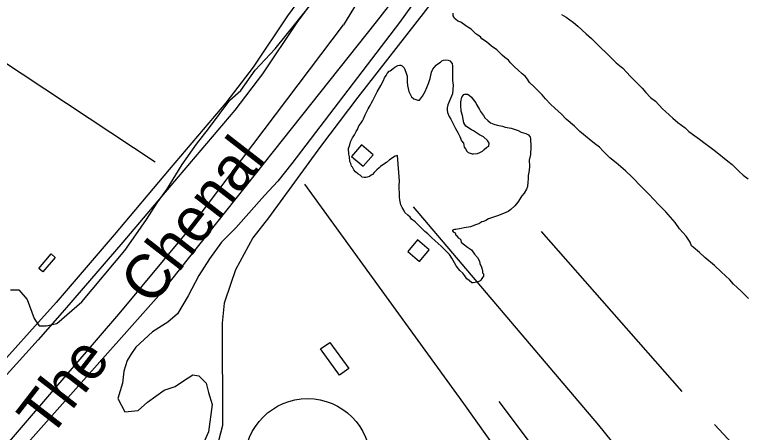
# Model space of a CAD drawing. Extents: x 3263578 to 3301413, y 764927 to 798602.
# Drawn here: x 3276220 to 3278134, y 776528 to 777624 of the extents above; entities that cross this region are included whole.
import ezdxf

# ---------------------------------------------------------------- set-up
doc = ezdxf.new("R2010")
doc.units = 0
for name, color, linetype in [('V-BLDG-OTLN', 7, 'Continuous'), ('V-RIVR-IDEN', 7, 'Continuous'), ('V-ROAD-CNTR', 7, 'Continuous'), ('V-ROAD-IDEN', 7, 'Continuous'), ('V-SITE-VEGE', 7, 'Continuous'), ('V-TOPO-SHOR', 7, 'Continuous')]:
    doc.layers.add(name, color=color, linetype=linetype)

msp = doc.modelspace()

# ---------------------------------------------------------------- linework, layer by layer
at = {"layer": 'V-BLDG-OTLN'}
for points in [[(3277129.6, 777282.6), (3277103.6, 777252.2), (3277134.1, 777226.2), (3277160, 777256.6)], [(3277276.7, 777033), (3277250.8, 777002.6), (3277281.2, 776976.6), (3277307.2, 777007.1)], [(3276326.1, 776987.2), (3276293.7, 776949.1), (3276283, 776958.2), (3276315.4, 776996.2)], [(3277071.9, 776678.4), (3277022.2, 776747.1), (3277046.3, 776764.5), (3277096, 776695.9)]]:
    msp.add_lwpolyline(points, close=True, dxfattribs=at)
at = {"layer": 'V-ROAD-CNTR'}
for points in [[(3277714.9, 778198.6), (3277529.7, 777962.3), (3277399.1, 777774.5), (3277297.3, 777634.4), (3277120, 777407.6), (3277022.1, 777278.4), (3276885.8, 777090.8), (3276844.4, 777038.2)], [(3277194.8, 777970.7), (3277056, 777784.8), (3276935.6, 777620.8), (3276845.7, 777486), (3276773.8, 777392.2), (3276625.5, 777218), (3276480.6, 777046.5), (3276328.4, 776869.2), (3276259.2, 776790.9), (3276145.3, 776665.7), (3276078.7, 776600.9), (3276001.2, 776511.3), (3275907.5, 776403.5), (3275821.9, 776296.9), (3275728.7, 776181.5), (3275680.8, 776116.1), (3275632.5, 776068.6), (3275515.4, 775977.6), (3275428.3, 775913), (3275327.1, 775831.8)], [(3277218.8, 777952.7), (3277080.1, 777766.9), (3276960.2, 777603.6), (3276870.1, 777468.6), (3276797.2, 777373.4), (3276648.4, 777198.6), (3276503.4, 777027.1), (3276351, 776849.5), (3276281.5, 776770.9), (3276166.9, 776644.8), (3276100.5, 776580.2), (3276023.8, 776491.6), (3275930.5, 776384.3), (3275845.3, 776278.1), (3275752.5, 776163.2), (3275703.5, 776096.4), (3275652.3, 776046), (3275533.6, 775953.7), (3275446.6, 775889.2), (3275376.6, 775833.1)], [(3276844.4, 777038.2), (3276799, 776954.4), (3276787, 776918.4), (3276769, 776866.9), (3276764, 776815.1), (3276764.8, 776546.6), (3276754.9, 776506.2), (3276736.4, 776456.2), (3276718.2, 776409.9), (3276692.4, 776372.3), (3276649.2, 776322.2), (3276604.9, 776260.7), (3276427.5, 776073.9), (3276212.2, 775832.8)]]:
    msp.add_lwpolyline(points, dxfattribs=at)
at = {"layer": 'V-ROAD-IDEN'}
msp.add_circle((3276988.1, 776451.9), 165, dxfattribs=at)
at = {"layer": 'V-SITE-VEGE'}
for p, q in [((3277410.4, 777853.7), (3277228.9, 777603.2)), ((3276903.4, 777534.4), (3277066.1, 777737.9)), ((3277369.9, 777621.1), (3277369.8, 777627.3)), ((3277372, 777618.1), (3277369.9, 777621.1)), ((3277373, 777614), (3277372, 777618.1)), ((3277376.1, 777612), (3277373, 777614)), ((3277382.3, 777607), (3277376.1, 777612)), ((3277389.5, 777604), (3277382.3, 777607)), ((3277653.5, 777623.9), (3277665.8, 777616.9)), ((3277665.8, 777616.9), (3277676.1, 777609.9)), ((3277676.1, 777609.9), (3277685.3, 777602.8)), ((3277228.9, 777603.2), (3276947.2, 777233.8)), ((3277402.8, 777594.9), (3277389.5, 777604)), ((3277408, 777590.9), (3277402.8, 777594.9)), ((3277417.2, 777585.9), (3277408, 777590.9)), ((3277685.3, 777602.8), (3277696.6, 777593.7)), ((3277696.6, 777593.7), (3277718.3, 777573.6)), ((3277429.5, 777573.8), (3277417.2, 777585.9)), ((3277434.7, 777569.7), (3277429.5, 777573.8)), ((3277441.9, 777565.7), (3277434.7, 777569.7)), ((3277718.3, 777573.6), (3277732.7, 777561.5)), ((3277445, 777560.7), (3277441.9, 777565.7)), ((3277457.3, 777552.6), (3277445, 777560.7)), ((3277470.7, 777541.5), (3277457.3, 777552.6)), ((3277732.7, 777561.5), (3277755.3, 777538.2)), ((3276850.2, 777478), (3276903.4, 777534.4)), ((3277484, 777531.5), (3277470.7, 777541.5)), ((3277498.5, 777517.3), (3277484, 777531.5)), ((3277755.3, 777538.2), (3277772.8, 777522.1)), ((3277505.7, 777511.3), (3277498.5, 777517.3)), ((3277514.9, 777504.2), (3277505.7, 777511.3)), ((3277772.8, 777522.1), (3277797.6, 777497.8)), ((3277520.1, 777497.1), (3277514.9, 777504.2)), ((3277530.4, 777487), (3277520.1, 777497.1)), ((3277797.6, 777497.8), (3277815, 777483.7)), ((3276812.7, 777424.8), (3276850.2, 777478)), ((3277539.6, 777479), (3277530.4, 777487)), ((3277551, 777468.9), (3277539.6, 777479)), ((3277815, 777483.7), (3277834.6, 777461.5)), ((3277558.2, 777462.8), (3277551, 777468.9)), ((3277564.4, 777454.7), (3277558.2, 777462.8)), ((3277569.6, 777445.6), (3277564.4, 777454.7)), ((3277834.6, 777461.5), (3277865.6, 777431.2)), ((3277581.9, 777434.5), (3277569.6, 777445.6)), ((3277603.5, 777413.3), (3277581.9, 777434.5)), ((3276784.5, 777399.7), (3276812.7, 777424.8)), ((3277865.6, 777431.2), (3277874.8, 777420)), ((3277874.8, 777420), (3277887.2, 777406.9)), ((3276756.3, 777362.2), (3276784.5, 777399.7)), ((3277611.8, 777403.2), (3277603.5, 777413.3)), ((3277625.2, 777389), (3277611.8, 777403.2)), ((3277887.2, 777406.9), (3277900.6, 777396.8)), ((3277900.6, 777396.8), (3277919.1, 777376.6)), ((3277636.5, 777378.9), (3277625.2, 777389)), ((3277654, 777362.8), (3277636.5, 777378.9)), ((3277919.1, 777376.6), (3277926.4, 777369.5)), ((3276728.2, 777324.6), (3276756.3, 777362.2)), ((3277666.4, 777349.6), (3277654, 777362.8)), ((3277926.4, 777369.5), (3277945.9, 777352.4)), ((3277688, 777331.5), (3277666.4, 777349.6)), ((3277945.9, 777352.4), (3277959.3, 777341.3)), ((3277959.3, 777341.3), (3277977.8, 777327.2)), ((3276696.9, 777283.9), (3276728.2, 777324.6)), ((3277702.4, 777317.3), (3277688, 777331.5)), ((3277977.8, 777327.2), (3277988.1, 777317.1)), ((3277726.1, 777297.2), (3277702.4, 777317.3)), ((3277988.1, 777317.1), (3278003.5, 777306)), ((3278003.5, 777306), (3278015.8, 777297)), ((3276659.3, 777230.7), (3276696.9, 777283.9)), ((3277740.5, 777286.1), (3277726.1, 777297.2)), ((3277753.8, 777276), (3277740.5, 777286.1)), ((3278015.8, 777297), (3278030.2, 777285.9)), ((3278030.2, 777285.9), (3278040.5, 777278.8)), ((3277763.1, 777265.9), (3277753.8, 777276)), ((3277780.6, 777248.7), (3277763.1, 777265.9)), ((3278040.5, 777278.8), (3278058, 777265.7)), ((3278058, 777265.7), (3278089.8, 777239.5)), ((3277797.1, 777235.6), (3277780.6, 777248.7)), ((3276618.6, 777164.9), (3276659.3, 777230.7)), ((3276947.2, 777233.8), (3276909.7, 777186.8)), ((3277821.8, 777214.4), (3277797.1, 777235.6)), ((3278089.8, 777239.5), (3278101.2, 777230.5)), ((3278101.2, 777230.5), (3278118.7, 777213.3)), ((3277839.3, 777197.3), (3277821.8, 777214.4)), ((3278118.7, 777213.3), (3278130, 777203.2)), ((3276909.7, 777186.8), (3276875.2, 777149.3)), ((3277864, 777172), (3277839.3, 777197.3)), ((3278130, 777203.2), (3278143.4, 777193.1)), ((3277882.6, 777152.8), (3277864, 777172)), ((3276593.6, 777130.5), (3276618.6, 777164.9)), ((3276875.2, 777149.3), (3276800.1, 777064.7)), ((3277909.4, 777125.5), (3277882.6, 777152.8)), ((3276565.4, 777086.7), (3276593.6, 777130.5)), ((3277927.9, 777106.3), (3277909.4, 777125.5)), ((3277951.7, 777079), (3277927.9, 777106.3)), ((3276537.3, 777046), (3276565.4, 777086.7)), ((3277963.1, 777061.8), (3277951.7, 777079)), ((3276800.1, 777064.7), (3276762.6, 777027.2)), ((3277980.6, 777042.6), (3277963.1, 777061.8)), ((3276509.1, 777005.3), (3276537.3, 777046)), ((3277990.9, 777027.4), (3277980.6, 777042.6)), ((3276762.6, 777027.2), (3276731.3, 776983.3)), ((3277995.1, 777017.2), (3277990.9, 777027.4)), ((3277999.2, 777014.2), (3277995.1, 777017.2)), ((3278015.7, 777000.1), (3277999.2, 777014.2)), ((3276396.5, 776870.6), (3276509.1, 777005.3)), ((3278030.1, 776987), (3278015.7, 777000.1)), ((3276731.3, 776983.3), (3276703.1, 776939.5)), ((3278054.8, 776965.8), (3278030.1, 776987)), ((3278072.3, 776949.6), (3278054.8, 776965.8)), ((3276703.1, 776939.5), (3276675, 776886.3)), ((3278095, 776928.4), (3278072.3, 776949.6)), ((3278105.3, 776917.3), (3278095, 776928.4)), ((3278114.5, 776908.2), (3278105.3, 776917.3)), ((3276208.7, 776901.9), (3276230.6, 776901.9)), ((3276230.6, 776901.9), (3276252.5, 776876.9)), ((3278124.8, 776899.1), (3278114.5, 776908.2)), ((3278144.4, 776879.9), (3278124.8, 776899.1)), ((3276675, 776886.3), (3276646.8, 776839.3)), ((3276252.5, 776876.9), (3276271.3, 776826.8)), ((3276330.7, 776814.3), (3276396.5, 776870.6)), ((3276271.3, 776826.8), (3276283.8, 776808)), ((3276646.8, 776839.3), (3276621.8, 776817.4)), ((3276283.8, 776808), (3276302.6, 776808)), ((3276302.6, 776808), (3276330.7, 776814.3)), ((3276621.8, 776817.4), (3276581.1, 776792.4)), ((3276581.1, 776792.4), (3276537.3, 776751.7)), ((3276537.3, 776751.7), (3276524.8, 776732.9)), ((3276524.8, 776732.9), (3276515.4, 776717.2)), ((3276515.4, 776717.2), (3276506, 776689.1)), ((3276506, 776689.1), (3276502.9, 776657.7)), ((3276662.5, 776664), (3276687.5, 776679.7)), ((3276687.5, 776679.7), (3276703.1, 776676.5)), ((3276703.1, 776676.5), (3276721.9, 776657.7)), ((3276502.9, 776657.7), (3276490.3, 776617)), ((3276612.4, 776639), (3276640.6, 776648.4)), ((3276640.6, 776648.4), (3276662.5, 776664)), ((3276721.9, 776657.7), (3276728.2, 776632.7)), ((3276568.6, 776607.7), (3276612.4, 776639)), ((3276728.2, 776632.7), (3276737.6, 776601.4)), ((3276490.3, 776617), (3276509.1, 776582.6)), ((3276543.5, 776585.7), (3276568.6, 776607.7)), ((3276737.6, 776601.4), (3276728.2, 776529.4)), ((3276509.1, 776582.6), (3276543.5, 776585.7)), ((3276728.2, 776529.4), (3276700, 776466.8))]:
    msp.add_line(p, q, dxfattribs=at)
for points in [[(3277446.9, 776946.5), (3277449, 776944.5), (3277449.1, 776938.4), (3277447.1, 776934.3), (3277443, 776929.1), (3277442, 776927.1), (3277437, 776924), (3277431.9, 776921.9), (3277422.7, 776920.8), (3277418.6, 776920.7), (3277411.4, 776926.8), (3277405.3, 776930.8), (3277400.1, 776938.9), (3277394.9, 776946), (3277387.7, 776953.1), (3277377.4, 776965.2), (3277373.2, 776973.3), (3277366, 776985.5), (3277359.8, 776994.6), (3277347.4, 777007.8), (3277338.1, 777016.9), (3277322.7, 777031), (3277313.4, 777039.1), (3277303.1, 777049.2), (3277295.9, 777055.2), (3277270.2, 777080.5), (3277260.9, 777087.5), (3277256.8, 777092.6), (3277250.6, 777097.6), (3277243.4, 777104.7), (3277240.3, 777110.8), (3277236.1, 777117.9), (3277233, 777125), (3277229.8, 777138.2), (3277228.7, 777145.3), (3277228.4, 777178), (3277229.3, 777184.1), (3277229.3, 777187.2), (3277223.5, 777254.5), (3277217.4, 777252.4), (3277203.3, 777243), (3277195.2, 777235.8), (3277183, 777228.6), (3277178.9, 777225.5), (3277175.9, 777222.4), (3277169.8, 777217.2), (3277162.8, 777210), (3277158.7, 777204.8), (3277154.7, 777202.8), (3277150.6, 777199.7), (3277144.5, 777197.6), (3277140.5, 777196.5), (3277136.4, 777196.5), (3277131.3, 777197.4), (3277126.1, 777202.5), (3277120, 777206.5), (3277113.8, 777211.5), (3277109.7, 777216.6), (3277105.5, 777223.7), (3277103.4, 777226.7), (3277101.3, 777233.9), (3277099.2, 777238.9), (3277098.1, 777251.2), (3277096, 777258.3), (3277095.8, 777272.6), (3277098.8, 777282.8), (3277100.8, 777290), (3277105.8, 777301.2), (3277110.8, 777308.4), (3277115.8, 777317.7), (3277118.8, 777322.8), (3277122.8, 777332), (3277126.8, 777337.2), (3277131.9, 777345.4), (3277134.9, 777350.5), (3277138.8, 777360.7), (3277146.8, 777377.1), (3277151.9, 777385.4), (3277155.9, 777392.5), (3277158.9, 777398.7), (3277162.9, 777405.9), (3277165.9, 777413), (3277170.9, 777421.3), (3277179.9, 777437.7), (3277186.9, 777451), (3277189.9, 777458.2), (3277193.9, 777464.3), (3277196.9, 777469.5), (3277202, 777475.6), (3277205, 777476.7), (3277212.1, 777482.9), (3277217.2, 777486), (3277224.3, 777490.1), (3277229.4, 777491.2), (3277232.4, 777491.2), (3277236.5, 777489.2), (3277241.7, 777484.2), (3277245.9, 777473), (3277249, 777462.8), (3277249.2, 777447.5), (3277250.3, 777438.4)], [(3277250.3, 777438.4), (3277253.5, 777422.1), (3277256.7, 777415), (3277260.8, 777407.9), (3277267, 777402.8), (3277277.2, 777399.9), (3277281.3, 777399.9), (3277289.3, 777410.2), (3277296.4, 777422.5), (3277305.3, 777443), (3277309.3, 777456.3), (3277313.2, 777472.6), (3277316.2, 777480.8), (3277325.3, 777491.1), (3277329.3, 777495.2), (3277336.4, 777499.4), (3277340.5, 777502.5), (3277344.5, 777504.6), (3277349.6, 777505.7), (3277356.8, 777504.7), (3277360.9, 777502.7), (3277367.1, 777495.6), (3277368.1, 777488.5), (3277368.5, 777450.7), (3277369.7, 777438.5), (3277367.8, 777416.1), (3277362.9, 777403.8), (3277355.9, 777387.4), (3277353.9, 777379.2), (3277354, 777373.1), (3277355.1, 777367), (3277359.2, 777356.8), (3277363.4, 777349.7), (3277375.9, 777325.3), (3277383.1, 777313.2), (3277387.3, 777304), (3277391.5, 777292.8), (3277396.7, 777286.8), (3277398.8, 777276.6)], [(3277398.8, 777276.6), (3277401.9, 777271.5), (3277406.1, 777265.4), (3277409.1, 777262.4), (3277412.2, 777261.4), (3277419.4, 777258.4), (3277423.5, 777258.5), (3277433.7, 777259.6), (3277439.7, 777262.7), (3277446.9, 777265.8), (3277450.9, 777270), (3277458, 777276.2), (3277463.1, 777279.3), (3277464, 777286.4), (3277459.9, 777293.5), (3277449.5, 777303.6), (3277439.3, 777308.6), (3277422.9, 777318.7), (3277417.7, 777321.7), (3277403.4, 777331.7), (3277398.2, 777339.8), (3277393.9, 777359.2), (3277390.7, 777370.4), (3277389.6, 777386.7), (3277389.5, 777394.8), (3277392.4, 777407.1), (3277395.4, 777411.2), (3277397.4, 777414.3), (3277400.5, 777415.4), (3277407.6, 777415.4), (3277411.7, 777412.4), (3277417.9, 777407.4), (3277422.1, 777401.3), (3277429.3, 777392.2), (3277431.4, 777388.1), (3277438.6, 777374.9), (3277441.8, 777369.9), (3277449, 777359.7), (3277453.1, 777353.6), (3277460.3, 777346.6), (3277467.5, 777340.5), (3277476.8, 777336.5), (3277485, 777333.6), (3277499.3, 777331.7), (3277506.4, 777328.7), (3277521.8, 777325.8), (3277540.2, 777319.8), (3277548.4, 777315.8), (3277560.7, 777311.9), (3277567.8, 777308.9), (3277572, 777302.8), (3277573, 777298.7), (3277573.3, 777277.3), (3277572.4, 777256.9), (3277569.5, 777242.6), (3277569.7, 777226.2), (3277568.8, 777215), (3277566.9, 777201.7), (3277566.9, 777193.6), (3277566, 777184.4), (3277565.1, 777173.1), (3277562.1, 777166), (3277556.1, 777155.7), (3277550, 777148.5), (3277539, 777132.1), (3277531.9, 777122.8), (3277520.8, 777112.5), (3277513.7, 777107.3), (3277501.5, 777102.1), (3277486.3, 777095.9), (3277462.9, 777088.5), (3277455.8, 777084.3), (3277449.7, 777081.2), (3277444.6, 777080.1), (3277437.5, 777075), (3277431.4, 777073.9), (3277415.1, 777067.6), (3277398.9, 777064.4), (3277390.7, 777063.3), (3277376.5, 777060.1), (3277373.4, 777060.1), (3277368.3, 777059), (3277368.3, 777056.9), (3277369.4, 777053.9), (3277375.5, 777051.9), (3277376.6, 777045.8), (3277378.6, 777044.8), (3277382.8, 777038.7), (3277388.9, 777034.7), (3277391.1, 777027.6), (3277396.2, 777022.5), (3277407.5, 777014.5), (3277417.8, 777007.4), (3277426.1, 776995.3), (3277433.3, 776987.2), (3277438.5, 776977), (3277439.6, 776970.9), (3277443.7, 776961.8), (3277445.8, 776955.7), (3277446.9, 776951.6), (3277446.9, 776946.5)]]:
    msp.add_lwpolyline(points, dxfattribs=at)
at = {"layer": 'V-TOPO-SHOR'}
for p, q in [((3276666.4, 777046.4), (3277082, 777597.2)), ((3277600.3, 777054.8), (3277969.3, 776635.5))]:
    msp.add_line(p, q, dxfattribs=at)
for points in [[(3278330.3, 779272.2), (3277930.9, 778699.5), (3277474.7, 778160.2), (3277185.7, 777766.5), (3277082, 777597.2)], [(3275798, 776029.4), (3275895.3, 776098.3), (3276604.9, 776895.2), (3277168.8, 777604.7), (3277784.5, 778391.6), (3278115.7, 778800.7), (3278211.5, 778942.7)], [(3276588, 777237), (3276065.7, 777582.1), (3276247.8, 777831.3)], [(3276979.8, 777179.5), (3277396.6, 776604.4), (3277827.8, 775998.2), (3277945.2, 775837.6)], [(3277264.9, 777119.6), (3277751.2, 776546.9), (3278081.8, 776137.1)], [(3275548.9, 775830), (3275796, 776027.1), (3276498.6, 776844.7), (3276666.4, 777046.4)], [(3277844.6, 776110.8), (3277688.9, 776345.6), (3277490.1, 776609.2)], [(3278704.8, 775832.8), (3278424.5, 776134.7), (3278232.8, 776362.3), (3278137, 776460.6), (3278055.5, 776549.2)]]:
    msp.add_lwpolyline(points, dxfattribs=at)

# ---------------------------------------------------------------- texts
at = {"layer": 'V-RIVR-IDEN'}
msp.add_text('The    Chenal', height=116, rotation=52.2243, dxfattribs=at).set_placement((3276311, 776508.6))

doc.saveas('drawing.dxf')
